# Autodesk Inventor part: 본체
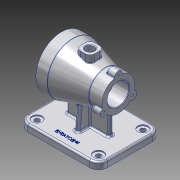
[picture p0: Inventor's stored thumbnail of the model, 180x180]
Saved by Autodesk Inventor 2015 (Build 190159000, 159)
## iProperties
Created: 2021-10
Part Number: 본체
Material: 알루미늄 6061
Document SubType Name: Modeling
Designer: 1019876
Density: 2.7 g/cm^3
Appearance: 알루미늄 - 평지
Mass: 1223.12 g
Surface Area: 899.639 cm^2
Volume: 453.008 cm^3
Author: 1019876
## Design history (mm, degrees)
sketch "스케치1"
  geometry: L1 (70, 55)-(-70, 55); L2 (-70, 55)-(-70, -55); L3 (-70, -55)-(70, -55); L4 (70, -55)-(70, 55); L5 (70, 55)-(-70, -55); L6 (-70, 55)-(70, -55); 1 further point
  constraints: 12 end point, 2 midpoint, 2 parallel, 1 horizontal, 1 perpendicular
  dimensions: "d0" = 140 distance of L3.end L2.end; "d1" = 110 distance of L2.end L1.end
extrude "돌출1" new body sketch "스케치1" distance "d2" = 12; taper "d3" = 0 deg
sketch "스케치2"
  geometry: L1 (-54, -39)-(54, -39); L2 (54, -39)-(54, 39); L3 (54, 39)-(-54, 39); L4 (-54, 39)-(-54, -39); L5 (-54, -39)-(54, 39); L6 (54, -39)-(-54, 39); 5 further points
  constraints: 12 end point, 4 coincident, 2 midpoint, 2 parallel, 1 horizontal, 1 perpendicular
  dimensions: "d4" = 108 distance of L3.end L2.end; "d5" = 78 distance of L2.end L1.end
hole "구멍1" sketch "스케치2" at (-54, 39), (54, -39), (54, 39), (-54, -39) diameter "d6" = 9; stored, may be unused: countersink angle "d10" = 90 deg, drill point angle "d12" = 118 deg; dims "d7" = 6, "d8" = 18, "d9" = 2, "d11" = 28
sketch "스케치3"
  geometry: L1 (-50, 82)-(50, 82); L2 (-50, 82)-(-50, 127); L3 (-50, 127)-(-30, 127); L4 (-30, 127)-(27, 111); L5 (27, 111)-(50, 111); L6 (50, 111)-(50, 82); L7 (70, 0)-(-70, 0) reference; 2 further points
  constraints: 12 end point, 1 horizontal, 1 midpoint, 1 parallel, 1 perpendicular, 1 vertical, 1 vertical alignment
  dimensions: "d13" = 90 diameter of L3 L1; "d15" = 82 distance between parallel lines of L7 L1; "d16" = 20 distance of L2.end L3.end; "d18" = 23 distance from line of L6 L4.end; "d19" = 100 distance between parallel lines of L6 L2; "d21" = 58 diameter of L5 L1
revolve "회전1" sketch "스케치3" stored, may be unused: angle "d22" = 90 deg
sketch "스케치4"
  geometry: L1 (0, 29)-(0, 0); L2 (0, 0)-(-25.115, -14.5); L3 (0, 0)-(25.115, -14.5); C1 r 7 at (0, 29); C2 r 7 at (-25.115, -14.5); C3 r 7 at (25.115, -14.5); A1 r 29 centre (0, 0) between (0, 29) and (-25.115, -14.5) reference; 1 further point
  constraints: 6 end point, 3 centre point, 3 point on circle, 2 coincident, 1 vertical, 1 vertical alignment
  dimensions: "d23" = 14 diameter of C1; "d24" = 120 deg angle of L2 L1; "d25" = 120 deg angle of L2 L3; "d26" = 14 diameter of C2; "d27" = 14 diameter of C3
extrude "돌출2" join sketch "스케치4" distance "d28" = 15; taper "d29" = 0 deg
node "작업 평면1"
sketch "스케치5"
  geometry: L1 (12.5, 12.5)-(-12.5, 12.5); L2 (-12.5, 12.5)-(-12.5, -12.5); L3 (-12.5, -12.5)-(12.5, -12.5); L4 (12.5, -12.5)-(12.5, 12.5); L5 (12.5, 12.5)-(-12.5, -12.5); L6 (-12.5, 12.5)-(12.5, -12.5); 1 further point
  constraints: 12 end point, 2 midpoint, 2 parallel, 1 horizontal, 1 perpendicular
  dimensions: "d31" = 25 distance of L3.end L2.end; "d32" = 25 distance of L2.end L1.end
extrude "돌출3" join sketch "스케치5" distance "d33" = 23.5; taper "d34" = 0 deg
sketch "스케치6"
  geometry: 2 further points
  constraints: 1 coincident
hole "구멍2" sketch "스케치6" at (0, 0) diameter "d35" = 15; stored, may be unused: countersink angle "d39" = 90 deg, drill point angle "d41" = 118 deg; dims "d36" = 6, "d37" = 18, "d38" = 2, "d40" = 38.25
sketch "스케치7"
  geometry: L1 (-50, 37)-(-50, 127) reference; L2 (-50, 82)-(50, 82); L3 (50, 73.94)-(50, 110.155) reference; L4 (-50, 82)-(-50, 113); L5 (-50, 113)-(-30, 113); L6 (-27, 110)-(-27, 110); L7 (-24, 107)-(17, 107); L8 (20, 104)-(20, 104); L9 (23, 101)-(50, 101); L10 (50, 82)-(50, 101); A1 r 3 centre (-30, 110) between (-27, 110) and (-30, 113); A2 r 3 centre (-24, 110) between (-27, 110) and (-24, 107); A3 r 3 centre (17, 104) between (20, 104) and (17, 107); A4 r 3 centre (23, 104) between (20, 104) and (23, 101); 3 further points
  constraints: 16 end point, 8 point on circle, 8 tangent, 7 point on line, 5 perpendicular, 4 centre point, 3 equal radius, 2 horizontal, 1 midpoint
  dimensions: "d42" = 23 distance between parallel lines of L6 L1; "d43" = 47 distance of point (-27, 107) point (20, 107); "d44" = 62 diameter of L5 L2; "d45" = 50 diameter of L7 L2; "d46" = 38 diameter of L9 L2; "d47" = 3 radius of A1
revolve "회전2" sketch "스케치7" stored, may be unused: angle "d48" = 90 deg
sketch "스케치8"
  geometry: L1 (-37, -4)-(37, -4); L2 (37, -4)-(37, 4); L3 (37, 4)-(-37, 4); L4 (-37, 4)-(-37, -4); L5 (-37, -4)-(37, 4); L6 (37, -4)-(-37, 4); L7 (-4, -24)-(4, -24); L8 (4, -24)-(4, 24); L9 (4, 24)-(-4, 24); L10 (-4, 24)-(-4, -24); L11 (-4, -24)-(4, 24); L12 (4, -24)-(-4, 24); 1 further point
  constraints: 24 end point, 4 midpoint, 4 parallel, 2 horizontal, 2 perpendicular
  dimensions: "d49" = 74 distance of L3.end L2.end; "d50" = 8 distance of L2.end L1.end; "d51" = 8 distance of L9.end L8.end; "d52" = 48 distance of L8.end L7.end
extrude "돌출4" join sketch "스케치8" stored distance "d53" = 23.5; taper "d54" = 0 deg
feature "면 기울기1" dims angle "d55" = 5 deg
feature "면 기울기2" dims angle "d56" = 5 deg
sketch "스케치9" dims "d57" = 80
  geometry: C1 r 31 at (0, 0) reference; C2 r 45 at (0, 0) reference; 8 further points
  constraints: 2 vertical alignment, 1 coincident, 9 other
  dimensions: "d60" = 360 deg dimension on point (0, 0) point (0, 40) (derived)
hole "구멍3" sketch "스케치9" at (0, 40), (-34.641, 20), (-34.641, -20), (0, -40), (34.641, -20), (34.641, 20) diameter "d62" = 3.242; stored, may be unused: countersink angle "d66" = 90 deg, drill point angle "d68" = 118 deg; dims "d63" = 9, "d64" = 18, "d65" = 2, "d67" = 11
sketch "스케치10"
  geometry: A1 r 7 centre (0, 0) between (6.949, -0.845) and (-6.949, -0.845) reference; A2 r 7 centre (-25.115, -43.5) between (-27.858, -37.06) and (-20.909, -49.095) reference; A3 r 7 centre (25.115, -43.5) between (20.909, -49.095) and (27.858, -37.06) reference; 4 further points
  constraints: 3 coincident
hole "구멍4" sketch "스케치10" at (0, 0), (-25.115, -43.5), (25.115, -43.5) diameter "d69" = 3.242; stored, may be unused: countersink angle "d73" = 90 deg, drill point angle "d75" = 118 deg; dims "d70" = 9, "d71" = 18, "d72" = 2, "d74" = 11
fillet "모깎기1" dims "d76" = 16
fillet "모깎기2" dims "d77" = 8
fillet "모깎기3" dims "d78" = 3
fillet "모깎기4" dims "d79" = 1
fillet "모깎기5" dims "d80" = 3
fillet "모깎기6" dims "d81" = 3
chamfer "모따기1" distance "d82" = 1; stored, may be unused: second distance "d83" = 2, angle "d84" = 45 deg
node "작업 평면2"
sketch "스케치11"
  geometry: L1 (-54, -55)-(54, -55) reference; 2 further points
  constraints: 1 vertical alignment, 1 other
  dimensions: "d86" = 15 distance from line of L1 point (0, -40)
feature "엠보싱1" sketch "스케치11" dims "d0" = 140, "d1" = 110, "d13" = 90, "d15" = 82, "d16" = 20, "d18" = 23, "d19" = 100, "d21" = 58, "d87" = 0.5, "d88" = 0
chamfer "모따기2" distance "d89" = 1; stored, may be unused: second distance "d90" = 2, angle "d91" = 45 deg
node "솔리드1"
other parameters: "d30" = 127
